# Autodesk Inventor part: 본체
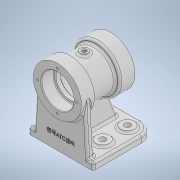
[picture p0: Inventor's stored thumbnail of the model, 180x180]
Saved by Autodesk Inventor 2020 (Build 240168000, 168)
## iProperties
Created: 2024-02
Part Number: 본체
Material: 일반
Document SubType Name: Modeling
Designer: oem
Density: 1 g/cm^3
Appearance: 기본값
Author: oem
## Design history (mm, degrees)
sketch "스케치1"
  geometry: C1 r 35 at (0, 0); 1 further point
  constraints: 1 centre point, 1 coincident
  dimensions: "d0" = 70 diameter of C1
extrude "돌출1" new body sketch "스케치1" stored distance "d1" = 78; taper "d2" = 0 deg
sketch "스케치2"
  geometry: L1 (35, 39)-(-35, 39) reference; L2 (-35, -39)-(35, -39) reference; L3 (0, 39)-(0, -39); L4 (35, 17)-(28.5, 17); L5 (28.5, -17)-(35, -17); L6 (35, 17)-(28.5, 17); L7 (28.5, 17)-(28.5, -17); L8 (28.5, -17)-(35, -17); L9 (35, -17)-(35, 17); L10 (0, -54.6)-(0, 54.6) reference; 2 further points
  constraints: 14 end point, 2 horizontal, 2 midpoint, 2 parallel, 1 perpendicular
  dimensions: "d4" = 22 distance between parallel lines of L1 L4; "d5" = 22 distance between parallel lines of L2 L5; "d6" = 28.5 distance between parallel lines of L7 L3
revolve "회전1" sketch "스케치2" stored, may be unused: angle "d7" = 90 deg
node "작업 평면1"
sketch "스케치3"
  geometry: C1 r 6 at (0, 0); 1 further point
  constraints: 1 centre point, 1 coincident
  dimensions: "d9" = 12 diameter of C1
extrude "돌출2" join sketch "스케치3" stored distance "d10" = 78; taper "d11" = 0 deg
sketch "스케치4"
  geometry: L1 (35, 39)-(-35, 39) reference; L2 (0, 39)-(23.5, 39); L3 (23.5, 39)-(23.5, 21); L4 (23.5, 21)-(0, 21); L5 (0, 21)-(0, 39); L6 (0, 21)-(20, 21); L7 (20, 21)-(20, 15.208); L8 (20, 15.208)-(0, 15.208); L9 (0, 15.208)-(0, 21); L10 (0, 15.208)-(20.5, 15.208); L11 (23.5, 12.208)-(23.5, -11.792); L12 (20.5, -14.792)-(0, -14.792); L13 (0, -14.792)-(0, 15.208); L14 (0, -14.792)-(20, -14.792); L15 (20, -14.792)-(20, -21); L16 (20, -21)-(0, -21); L17 (0, -21)-(0, -14.792); L18 (-35, -39)-(35, -39) reference; L19 (0, -21)-(23.5, -21); L20 (23.5, -21)-(23.5, -39); L21 (23.5, -39)-(0, -39); L22 (0, -39)-(0, -21); A1 r 3 centre (20.5, 12.208) between (23.5, 12.208) and (20.5, 15.208); A2 r 3 centre (20.5, -11.792) between (20.5, -14.792) and (23.5, -11.792); 7 further points
  constraints: 40 end point, 10 parallel, 5 horizontal, 5 perpendicular, 4 point on circle, 4 tangent, 2 centre point, 1 equal radius, 1 midpoint, 1 point on line
  dimensions: "d12" = 47 diameter of L3 L5; "d13" = 40 diameter of L7 L9; "d14" = 47 diameter of L11 L13; "d15" = 40 diameter of L15 L17; "d16" = 47 diameter of L20 L22; "d17" = 3 radius of A1; "d116" = 18 distance of L2.end L3.end; "d117" = 30 distance between parallel lines of L12 L8; "d118" = 18 distance between parallel lines of L21 L16
revolve "회전2" sketch "스케치4" stored, may be unused: angle "d18" = 90 deg
sketch "스케치5"
  geometry: C1 r 6 at (0, 0) reference
hole "구멍1" sketch "스케치5" at (0, 0) diameter "d19" = 5.1881; stored, may be unused: countersink angle "d23" = 90 deg, drill point angle "d25" = 0 deg; dims "d20" = 30, "d21" = 7, "d22" = 2, "d24" = 35
node "작업 평면2"
sketch "스케치6"
  geometry: L1 (35, 39)-(-35, 39) reference; L2 (47, 34)-(-47, 34); L3 (-47, 34)-(-47, -56); L4 (-47, -56)-(47, -56); L5 (47, -56)-(47, 34); 1 further point
  constraints: 8 end point, 2 parallel, 1 horizontal, 1 perpendicular
  dimensions: "d27" = 5 distance between parallel lines of L1 L2; "d28" = 90 distance of L2.end L3.end; "d29" = 94 distance of L3.end L4.end; "d30" = 47 distance from line of L3 point (0, 0)
extrude "돌출3" join sketch "스케치6" distance "d31" = 10; taper "d32" = 0 deg
fillet "모깎기1" dims "d33" = 20
sketch "스케치7"
  geometry: C1 r 10 at (-27, 36); A1 r 20 centre (-27, 36) between (-27, 56) and (-47, 36) reference; 1 further point
  constraints: 1 centre point, 1 coincident
  dimensions: "d34" = 20 diameter of C1
extrude "돌출4" join sketch "스케치7" distance "d35" = 3; taper "d36" = 0 deg
sketch "스케치8"
  geometry: C1 r 10 at (0, 0) reference; 1 further point
hole "구멍2" sketch "스케치8" at (0, 0) diameter "d37" = 9; stored, may be unused: countersink angle "d41" = 90 deg, drill point angle "d43" = 0 deg; dims "d38" = 30, "d39" = 7, "d40" = 2, "d42" = 35
sketch "스케치9"
  geometry: L1 (-70, -36)-(-70, 34) reference; L2 (-70, 34)-(-31.183, 34); L3 (-31.183, -29.872)-(-70, -44); L4 (-70, -36)-(-70, -56) reference; L5 (-70, -56)-(-80, -56) reference; L6 (-31.183, 20.313)-(-26.863, 20.313); L7 (-26.863, 20.313)-(-26.863, -20.747); L8 (-26.863, -20.747)-(-31.183, -20.747); L9 (-31.183, 34)-(-31.183, 20.313); L10 (-31.183, -20.747)-(-31.183, -29.872); 1 further point
  constraints: 14 end point, 2 horizontal, 2 perpendicular, 2 vertical, 1 point on line
  dimensions: "d50" = 12 distance from line of L3.end L5; "d51" = 70 deg angle of L1 L3
extrude "돌출5" join sketch "스케치9" stored distance "d52" = 10; taper "d53" = 0 deg
sketch "스케치10"
  geometry: L1 (94, 0)-(94, 10) reference; L2 (52, 10)-(94, 10) reference; L3 (0, 10)-(42, 10) reference; L4 (0, 0)-(0, 10) reference; L5 (81.945, 81.969)-(86, 10); L6 (12.055, 81.969)-(8, 10); L7 (8, 10)-(86, 10); L8 (0, 10)-(20, 10) reference; A1 r 35 centre (47, 80) between (42, 45.359) and (52, 45.359) reference; A2 r 35 centre (47, 80) between (52, 45.359) and (42, 45.359) reference; 2 further points
  constraints: 6 end point, 2 point on circle, 2 point on line, 2 tangent, 1 collinear
  dimensions: "d54" = 8 distance from line of L1 L5.end; "d55" = 8 distance from line of L4 L6.end
extrude "돌출6" join sketch "스케치10" distance "d56" = 10; taper "d57" = 0 deg
sketch "스케치11"
  geometry: C1 r 35 at (0, 0) reference; A1 r 28.5 centre (0, 0) between (-5, -28.058) and (5, -28.058); A2 r 28.5 centre (0, 0) between (5, -28.058) and (-5, -28.058) reference; 1 further point
  constraints: 1 centre point, 1 coincident, 1 point on circle
  dimensions: "d58" = 57 diameter of A1
hole "구멍3" sketch "스케치11" at (0, 28.5) diameter "d59" = 3.242; stored, may be unused: countersink angle "d63" = 90 deg, drill point angle "d65" = 118 deg; dims "d60" = 8, "d61" = 7, "d62" = 2, "d64" = 10
node "작업 평면3"
chamfer "모따기1" distance "d74" = 1; stored, may be unused: second distance "d75" = 2, angle "d76" = 45 deg
fillet "모깎기7" dims "d77" = 3
fillet "모깎기8" dims "d78" = 3
fillet "모깎기9" dims "d79" = 1
fillet "모깎기12" dims "d85" = 3
fillet "모깎기24" dims "d103" = 3
fillet "모깎기29" dims "d108" = 3
fillet "모깎기32" dims "d111" = 3
fillet "모깎기33" dims "d112" = 3
sketch "스케치15"
  geometry: L1 (-44, -80)-(44, -80) reference; L2 (-25.274, -60)-(22.061, -60); L3 (-20.514, -56.819)-(20.965, -56.819); L4 (20.965, -56.819)-(20.965, -62.823); L5 (20.965, -62.823)-(-20.514, -62.823); L6 (-20.514, -62.823)-(-20.514, -56.819)
  constraints: 2 end point, 1 horizontal, 2 other
  dimensions: "d113" = 20 distance between parallel lines of L2 L1
feature "엠보싱4" sketch "스케치15" dims "d114" = 0.5, "d115" = 0
fillet "모깎기34" dims "d119" = 3
node "솔리드1"
pattern_linear "직사각형 패턴1" dims "d46" = 54, "d49" = 36
pattern_circular "원형 패턴1" dims angle "d67" = 360 deg
mirror "미러1"
feature "A9D066F2-1C7D-4E18-AEED-F7BC21143FA4" dims "d19" = 5.1881, "d20" = 30, "d21" = 7, "d22" = 2, "d23" = 90 deg, "d24" = 35, "d25" = 0
other parameters: "d8" = 31.5
